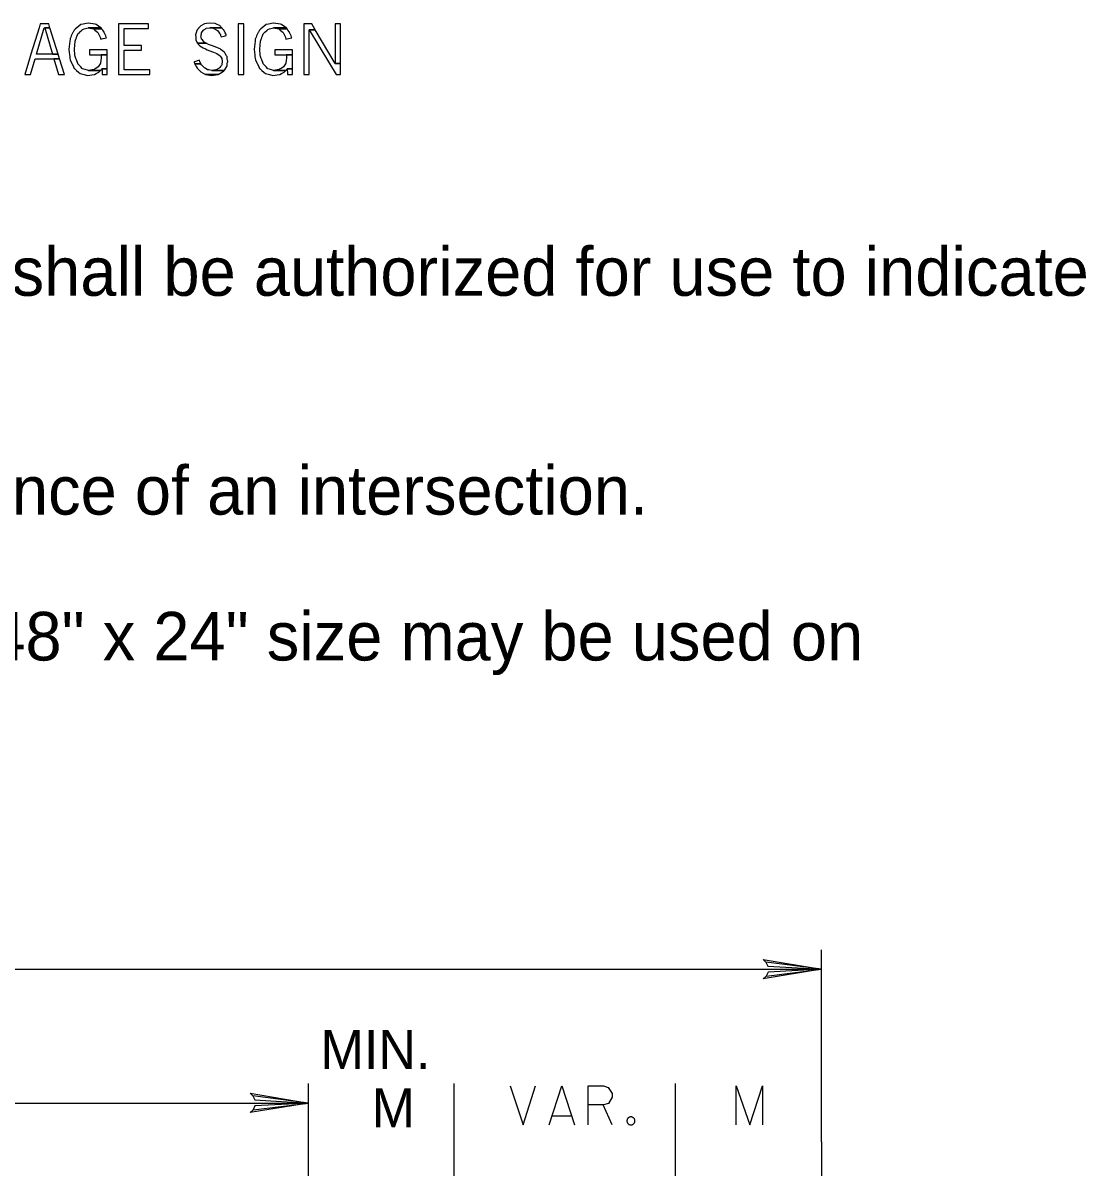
# Model space of a CAD drawing. Extents: x 0.011 to 0.188, y 0.004 to 0.261.
# Drawn here: x 0.1286 to 0.1837, y 0.1928 to 0.2525 of the extents above; entities that cross this region are included whole.
import ezdxf

# ---------------------------------------------------------------- set-up
doc = ezdxf.new("R2010")
doc.units = 0
doc.layers.add('1', color=7, linetype='Continuous')
doc.layers.add('3', color=7, linetype='Continuous')

# ---------------------------------------------------------------- blocks, each defined once
blk = doc.blocks.new('RARROW')
at = {"layer": '3'}
for p, q in [((-2.156, 0.285), (-2.2665, 0.384625)), ((-2.2665, 0.384625), (0, 0)), ((0, 0), (-2.2665, -0.379125)), ((-2.156, 0.285), (-2.075625, 0.12075)), ((0, 0), (-2.156, 0.285)), ((-2.14975, -0.2705), (0, 0)), ((-2.075625, 0.12075), (0, 0)), ((0, 0), (-2.074, -0.108)), ((-2.2665, -0.379125), (-2.14975, -0.2705)), ((-2.074, -0.108), (-2.14975, -0.2705))]:
    blk.add_line(p, q, dxfattribs=at)

msp = doc.modelspace()

# ---------------------------------------------------------------- linework, layer by layer
at = {"layer": '1'}
for points in [[(0.128928, 0.250665), (0.128676, 0.249848), (0.128982, 0.249848), (0.129217, 0.250665), (0.130482, 0.250665), (0.130407, 0.250909), (0.129286, 0.250909), (0.129679, 0.252276), (0.129986, 0.252276), (0.129926, 0.252474), (0.129485, 0.252474), (0.129424, 0.252276), (0.129002, 0.250909)], [(0.129719, 0.252276), (0.130111, 0.250909), (0.130407, 0.250909), (0.129986, 0.252276)], [(0.131765, 0.249846), (0.131933, 0.249806), (0.132281, 0.249846), (0.132286, 0.249848), (0.132377, 0.249895), (0.132525, 0.249972), (0.132605, 0.250058), (0.131975, 0.250058), (0.131811, 0.250104), (0.131668, 0.250144), (0.131647, 0.250166), (0.131578, 0.250239), (0.131431, 0.250396), (0.131423, 0.250417), (0.131354, 0.250603), (0.131322, 0.250687), (0.13129, 0.250774), (0.131282, 0.250871), (0.13126, 0.251147), (0.131258, 0.251171), (0.131295, 0.251581), (0.131334, 0.251689), (0.131343, 0.251714), (0.131355, 0.251747), (0.131368, 0.251786), (0.131392, 0.25185), (0.131428, 0.251949), (0.131507, 0.252028), (0.131519, 0.252041), (0.13163, 0.252151), (0.131665, 0.252186), (0.131764, 0.252212), (0.131763, 0.252212), (0.13196, 0.252264), (0.132634, 0.252264), (0.132626, 0.252275), (0.132376, 0.252436), (0.132332, 0.252464), (0.131958, 0.252516), (0.131957, 0.252516), (0.131714, 0.252464), (0.131579, 0.252436), (0.131384, 0.252275), (0.131371, 0.252264), (0.131308, 0.252212), (0.131276, 0.252186), (0.131234, 0.252151), (0.131181, 0.252041), (0.131176, 0.252028), (0.131138, 0.251949), (0.131092, 0.25185), (0.131061, 0.251786), (0.131043, 0.251747), (0.131028, 0.251714), (0.131024, 0.251689), (0.131012, 0.251581), (0.130964, 0.251171), (0.130961, 0.251147), (0.130995, 0.250871), (0.131006, 0.250774), (0.131016, 0.250687), (0.131027, 0.250603), (0.131118, 0.250417), (0.131129, 0.250396), (0.131206, 0.250239), (0.131242, 0.250166), (0.131267, 0.250144), (0.131313, 0.250104), (0.131367, 0.250058), (0.131465, 0.249972), (0.131554, 0.249895), (0.131754, 0.249848)], [(0.13196, 0.252264), (0.132244, 0.252212), (0.132672, 0.252212), (0.132634, 0.252264)], [(0.132606, 0.251714), (0.132614, 0.251689), (0.132743, 0.251714), (0.132742, 0.251714), (0.13291, 0.251747), (0.132898, 0.251786), (0.132878, 0.25185), (0.132835, 0.251949), (0.132801, 0.252028), (0.132795, 0.252041), (0.132716, 0.252151), (0.13269, 0.252186), (0.132672, 0.252212), (0.132244, 0.252212), (0.132275, 0.252186), (0.132317, 0.252151), (0.132447, 0.252041), (0.132463, 0.252028), (0.132502, 0.251949), (0.132552, 0.25185), (0.132584, 0.251786), (0.132596, 0.251747)], [(0.133545, 0.2501), (0.133545, 0.249848), (0.135154, 0.249848), (0.135154, 0.2501), (0.133833, 0.2501), (0.133833, 0.251105), (0.134726, 0.251105), (0.134726, 0.251349), (0.133833, 0.251349), (0.133833, 0.252226), (0.135093, 0.252226), (0.135093, 0.252474), (0.133545, 0.252474), (0.133545, 0.252226), (0.133545, 0.251349), (0.133545, 0.251105)], [(0.137604, 0.251524), (0.137629, 0.251469), (0.138086, 0.251469), (0.137979, 0.251524), (0.137882, 0.251639), (0.137846, 0.251682), (0.13782, 0.251798), (0.137811, 0.251844), (0.137816, 0.251875), (0.137819, 0.251898), (0.137829, 0.251954), (0.13783, 0.25196), (0.137839, 0.252013), (0.137916, 0.252129), (0.137929, 0.252149), (0.137941, 0.252157), (0.137959, 0.252168), (0.13808, 0.252242), (0.138083, 0.252243), (0.13827, 0.252273), (0.138885, 0.252273), (0.13882, 0.252341), (0.138798, 0.252364), (0.138578, 0.252469), (0.138543, 0.252486), (0.138263, 0.252516), (0.138263, 0.252516), (0.13809, 0.252486), (0.137992, 0.252469), (0.137803, 0.252364), (0.137761, 0.252341), (0.137705, 0.252273), (0.137681, 0.252243), (0.13768, 0.252242), (0.137619, 0.252168), (0.137611, 0.252157), (0.137608, 0.252149), (0.137602, 0.252129), (0.137568, 0.252013), (0.137552, 0.25196), (0.137551, 0.251954), (0.137534, 0.251898), (0.137535, 0.251875), (0.137538, 0.251844), (0.137541, 0.251798), (0.137549, 0.251682), (0.137552, 0.251639)], [(0.138841, 0.251844), (0.138859, 0.251798), (0.139014, 0.251844), (0.13912, 0.251875), (0.139113, 0.251898), (0.139095, 0.251954), (0.139093, 0.25196), (0.139065, 0.252013), (0.139004, 0.252129), (0.138994, 0.252149), (0.13899, 0.252157), (0.138984, 0.252168), (0.138914, 0.252242), (0.138913, 0.252243), (0.138885, 0.252273), (0.13827, 0.252273), (0.138459, 0.252243), (0.13847, 0.252242), (0.138601, 0.252168), (0.13862, 0.252157), (0.138633, 0.252149), (0.138669, 0.252129), (0.138755, 0.252013), (0.138794, 0.25196), (0.138799, 0.251954), (0.13882, 0.251898), (0.13883, 0.251875)], [(0.139736, 0.252474), (0.139736, 0.249848), (0.14003, 0.249848), (0.14003, 0.252474)], [(0.141367, 0.249846), (0.141535, 0.249806), (0.141883, 0.249846), (0.141888, 0.249848), (0.141979, 0.249895), (0.142127, 0.249972), (0.142207, 0.250058), (0.141577, 0.250058), (0.141413, 0.250104), (0.14127, 0.250144), (0.141249, 0.250166), (0.14118, 0.250239), (0.141033, 0.250396), (0.141025, 0.250417), (0.140956, 0.250603), (0.140924, 0.250687), (0.140892, 0.250774), (0.140884, 0.250871), (0.140862, 0.251147), (0.14086, 0.251171), (0.140897, 0.251581), (0.140936, 0.251689), (0.140945, 0.251714), (0.140957, 0.251747), (0.14097, 0.251786), (0.140994, 0.25185), (0.14103, 0.251949), (0.141109, 0.252028), (0.141121, 0.252041), (0.141232, 0.252151), (0.141267, 0.252186), (0.141366, 0.252212), (0.141365, 0.252212), (0.141562, 0.252264), (0.142236, 0.252264), (0.142228, 0.252275), (0.141979, 0.252436), (0.141934, 0.252464), (0.14156, 0.252516), (0.141559, 0.252516), (0.141316, 0.252464), (0.141181, 0.252436), (0.140986, 0.252275), (0.140973, 0.252264), (0.14091, 0.252212), (0.140878, 0.252186), (0.140836, 0.252151), (0.140784, 0.252041), (0.140778, 0.252028), (0.14074, 0.251949), (0.140694, 0.25185), (0.140663, 0.251786), (0.140645, 0.251747), (0.14063, 0.251714), (0.140626, 0.251689), (0.140614, 0.251581), (0.140566, 0.251171), (0.140563, 0.251147), (0.140597, 0.250871), (0.140608, 0.250774), (0.140618, 0.250687), (0.140629, 0.250603), (0.14072, 0.250417), (0.140731, 0.250396), (0.140808, 0.250239), (0.140844, 0.250166), (0.140869, 0.250144), (0.140915, 0.250104), (0.140969, 0.250058), (0.141068, 0.249972), (0.141156, 0.249895), (0.141356, 0.249848)], [(0.141562, 0.252264), (0.141846, 0.252212), (0.142274, 0.252212), (0.142236, 0.252264)], [(0.142208, 0.251714), (0.142216, 0.251689), (0.142345, 0.251714), (0.142344, 0.251714), (0.142512, 0.251747), (0.1425, 0.251786), (0.142481, 0.25185), (0.142437, 0.251949), (0.142403, 0.252028), (0.142397, 0.252041), (0.142318, 0.252151), (0.142292, 0.252186), (0.142274, 0.252212), (0.141846, 0.252212), (0.141877, 0.252186), (0.141919, 0.252151), (0.14205, 0.252041), (0.142065, 0.252028), (0.142104, 0.251949), (0.142154, 0.25185), (0.142186, 0.251786), (0.142198, 0.251747)], [(0.143147, 0.250424), (0.143147, 0.249848), (0.14342, 0.249848), (0.14342, 0.250424), (0.14342, 0.252171), (0.143736, 0.252171), (0.143558, 0.252474), (0.143147, 0.252474), (0.143147, 0.252171)], [(0.144466, 0.250424), (0.144812, 0.249848), (0.145037, 0.249848), (0.145037, 0.250424), (0.144764, 0.250424), (0.143736, 0.252171), (0.14342, 0.252171)], [(0.144764, 0.252474), (0.144764, 0.250424), (0.145037, 0.250424), (0.145037, 0.252474)], [(0.132036, 0.251122), (0.132036, 0.250871), (0.132944, 0.250871), (0.132944, 0.251122)], [(0.138581, 0.250084), (0.13837, 0.250056), (0.139016, 0.250056), (0.139035, 0.250084), (0.139042, 0.250095), (0.139092, 0.250172), (0.139103, 0.250188), (0.139103, 0.250188), (0.139116, 0.250208), (0.139152, 0.250262), (0.139163, 0.250322), (0.139169, 0.250358), (0.139176, 0.250402), (0.139193, 0.250496), (0.139195, 0.250507), (0.139196, 0.250513), (0.139199, 0.250531), (0.139176, 0.250684), (0.139161, 0.250789), (0.139139, 0.250825), (0.13907, 0.250938), (0.139024, 0.251014), (0.138999, 0.251032), (0.138856, 0.251136), (0.138808, 0.251172), (0.138671, 0.25123), (0.13854, 0.251287), (0.138407, 0.251335), (0.138207, 0.251407), (0.138086, 0.251469), (0.137629, 0.251469), (0.137686, 0.251407), (0.137753, 0.251335), (0.137829, 0.251287), (0.137917, 0.25123), (0.138052, 0.251172), (0.138132, 0.251136), (0.138416, 0.251032), (0.138459, 0.251014), (0.138633, 0.250938), (0.138802, 0.250825), (0.138824, 0.250789), (0.138892, 0.250684), (0.138915, 0.250531), (0.138918, 0.250513), (0.138916, 0.250507), (0.138914, 0.250496), (0.138895, 0.250402), (0.138885, 0.250358), (0.138878, 0.250322), (0.138829, 0.250262), (0.138785, 0.250208), (0.138768, 0.250188), (0.138756, 0.250172), (0.138602, 0.250095)], [(0.141638, 0.251122), (0.141638, 0.250871), (0.142546, 0.250871), (0.142546, 0.251122)], [(0.130193, 0.250665), (0.130428, 0.249848), (0.130734, 0.249848), (0.130482, 0.250665)], [(0.132267, 0.250104), (0.131975, 0.250058), (0.132605, 0.250058), (0.132649, 0.250104), (0.132679, 0.250136), (0.132944, 0.250136), (0.132944, 0.250144), (0.132944, 0.250166), (0.132944, 0.250239), (0.132944, 0.250396), (0.132944, 0.250417), (0.132944, 0.250603), (0.132944, 0.250687), (0.132944, 0.250774), (0.132944, 0.250871), (0.132642, 0.250871), (0.132642, 0.250774), (0.132642, 0.250687), (0.132629, 0.250603), (0.132603, 0.250417), (0.132589, 0.250396), (0.132482, 0.250239), (0.132366, 0.250166), (0.132331, 0.250144), (0.132317, 0.250136)], [(0.137461, 0.250496), (0.137495, 0.250402), (0.137811, 0.250402), (0.137763, 0.250496), (0.13776, 0.250507), (0.137758, 0.250513), (0.137752, 0.250531), (0.137752, 0.250531), (0.137732, 0.250595), (0.137731, 0.250595), (0.137532, 0.250531), (0.137475, 0.250513), (0.137457, 0.250507)], [(0.1378, 0.249982), (0.138052, 0.249853), (0.138708, 0.249853), (0.138926, 0.249982), (0.138994, 0.250022), (0.139016, 0.250056), (0.13837, 0.250056), (0.138213, 0.250084), (0.138213, 0.250084), (0.138152, 0.250095), (0.138026, 0.250172), (0.138, 0.250188), (0.137967, 0.250208), (0.137919, 0.250262), (0.137866, 0.250322), (0.137866, 0.250322), (0.137834, 0.250358), (0.137811, 0.250402), (0.137494, 0.250402), (0.137517, 0.250358), (0.137536, 0.250322), (0.137567, 0.250262), (0.137595, 0.250208), (0.137606, 0.250188), (0.13762, 0.250172), (0.137693, 0.250095), (0.137703, 0.250084), (0.13773, 0.250056), (0.137761, 0.250022)], [(0.141869, 0.250104), (0.141577, 0.250058), (0.142207, 0.250058), (0.142251, 0.250104), (0.142281, 0.250136), (0.142546, 0.250136), (0.142546, 0.250144), (0.142546, 0.250166), (0.142546, 0.250239), (0.142546, 0.250396), (0.142546, 0.250417), (0.142546, 0.250603), (0.142546, 0.250687), (0.142546, 0.250774), (0.142546, 0.250871), (0.142244, 0.250871), (0.142244, 0.250774), (0.142244, 0.250687), (0.142231, 0.250603), (0.142205, 0.250417), (0.142191, 0.250396), (0.142084, 0.250239), (0.141968, 0.250166), (0.141933, 0.250144), (0.141919, 0.250136)], [(0.13269, 0.249895), (0.132693, 0.249848), (0.132944, 0.249848), (0.132944, 0.249895), (0.132944, 0.249972), (0.132944, 0.250058), (0.132944, 0.250104), (0.132944, 0.250136), (0.132679, 0.250136), (0.132681, 0.250104), (0.132683, 0.250058), (0.132687, 0.249972)], [(0.138058, 0.249853), (0.138362, 0.249806), (0.138707, 0.249853), (0.138708, 0.249853), (0.138052, 0.249853)], [(0.142292, 0.249895), (0.142295, 0.249848), (0.142546, 0.249848), (0.142546, 0.249895), (0.142546, 0.249972), (0.142546, 0.250058), (0.142546, 0.250104), (0.142546, 0.250136), (0.142281, 0.250136), (0.142283, 0.250104), (0.142285, 0.250058), (0.142289, 0.249972)]]:
    msp.add_lwpolyline(points, close=True, dxfattribs=at)
at = {"layer": '3'}
for p, q in [((0.169961, 0.194534), (0.169961, 0.204488)), ((0.111148, 0.20348), (0.169961, 0.20348)), ((0.143375, 0.19277), (0.143375, 0.197558)), ((0.150935, 0.19277), (0.150935, 0.197558)), ((0.162401, 0.19277), (0.162401, 0.197558)), ((0.140499, 0.196927), (0.140351, 0.197058)), ((0.140351, 0.197058), (0.143375, 0.19655)), ((0.140499, 0.196927), (0.140606, 0.19671)), ((0.143375, 0.19655), (0.140499, 0.196927)), ((0.140606, 0.19671), (0.143375, 0.19655)), ((0.114773, 0.19655), (0.143375, 0.19655)), ((0.139343, 0.19655), (0.143375, 0.19655)), ((0.143375, 0.19655), (0.140351, 0.19605)), ((0.140351, 0.19605), (0.140507, 0.196193)), ((0.140507, 0.196193), (0.143375, 0.19655)), ((0.140608, 0.196408), (0.140507, 0.196193)), ((0.143375, 0.19655), (0.140608, 0.196408)), ((0.169961, 0.194534), (0.169961, 0.19277))]:
    msp.add_line(p, q, dxfattribs=at)
for points in [[(0.153833, 0.197433), (0.1545, 0.195416), (0.155151, 0.197433)], [(0.15585, 0.195416), (0.156516, 0.197433), (0.157167, 0.195416)], [(0.157866, 0.195416), (0.157866, 0.197433), (0.158676, 0.197433), (0.158914, 0.197353), (0.15912, 0.197036), (0.15912, 0.196845), (0.15893, 0.196528), (0.158676, 0.196448), (0.157866, 0.196448)], [(0.165551, 0.195416), (0.165551, 0.197433), (0.16625, 0.195416), (0.166901, 0.197433), (0.166901, 0.195416)], [(0.15912, 0.195416), (0.15866, 0.196448)], [(0.156008, 0.195893), (0.157009, 0.195893)], [(0.160295, 0.195623), (0.160294, 0.195644), (0.16029, 0.195666), (0.160285, 0.195686), (0.160277, 0.195707), (0.160267, 0.195726), (0.160255, 0.195744), (0.160242, 0.195761), (0.160227, 0.195776), (0.16021, 0.19579), (0.160192, 0.195801), (0.160172, 0.195811), (0.160152, 0.195819), (0.160131, 0.195825), (0.16011, 0.195828), (0.160088, 0.195829), (0.160067, 0.195828), (0.160046, 0.195825), (0.160025, 0.195819), (0.160005, 0.195811), (0.159985, 0.195801), (0.159967, 0.19579), (0.15995, 0.195776), (0.159935, 0.195761), (0.159922, 0.195744), (0.15991, 0.195726), (0.1599, 0.195707), (0.159892, 0.195686), (0.159887, 0.195666), (0.159883, 0.195644), (0.159882, 0.195623), (0.159883, 0.195601), (0.159887, 0.19558), (0.159892, 0.195559), (0.1599, 0.195539), (0.15991, 0.19552), (0.159922, 0.195501), (0.159935, 0.195485), (0.15995, 0.195469), (0.159967, 0.195456), (0.159985, 0.195444), (0.160005, 0.195434), (0.160025, 0.195427), (0.160046, 0.195421), (0.160067, 0.195417), (0.160088, 0.195416), (0.16011, 0.195417), (0.160131, 0.195421), (0.160152, 0.195427), (0.160172, 0.195434), (0.160192, 0.195444), (0.16021, 0.195456), (0.160227, 0.195469), (0.160242, 0.195485), (0.160255, 0.195501), (0.160267, 0.19552), (0.160277, 0.195539), (0.160285, 0.195559), (0.16029, 0.19558), (0.160294, 0.195601), (0.160295, 0.195623)]]:
    msp.add_lwpolyline(points, dxfattribs=at)

# ---------------------------------------------------------------- block references
at = {"layer": '3', "xscale": 0.0013342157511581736, "yscale": 0.0013198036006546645}
msp.add_blockref('RARROW', (0.169961, 0.20348), dxfattribs=at)

# ---------------------------------------------------------------- texts
at = {"layer": '3'}
for s, height, p in [('   (a) Justification.  The Triple-Line Destination Mileage Sign (D1-3A) shall be authorized for use to indicate', 0.002519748, (0.025187, 0.238382)), ('   (b) Placement.  The D1-3A sign should generally be placed in advance of an intersection.', 0.00251975, (0.025187, 0.227042)), ('   (c) Size.  The standard size of D1-3A sign shall be 72" x 36".  The 48" x 24" size may be used on', 0.00251975, (0.025187, 0.219482)), ('MIN.', 0.0020163, (0.144005, 0.198314)), ('M', 0.002016, (0.146651, 0.19529))]:
    msp.add_text(s, height=height, dxfattribs=at).set_placement(p)

doc.saveas('drawing.dxf')
